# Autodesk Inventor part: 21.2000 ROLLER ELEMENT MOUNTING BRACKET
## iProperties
Created: 2007-05
Part Number: 21.2000 ROLLER ELEMENT MOUNTING BRACKET
Material: Steel
Document SubType Name: Modeling
Designer: Andy Moles
Density: 7.85 g/cm^3
Author: Andy Moles
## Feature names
1. Base1
2. Extrusion1
